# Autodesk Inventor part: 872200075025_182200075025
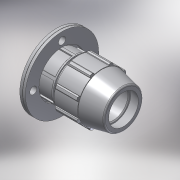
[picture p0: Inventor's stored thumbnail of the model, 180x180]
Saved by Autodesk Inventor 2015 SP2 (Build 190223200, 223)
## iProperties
Created: 2017-02
Part Number: 872200075025_182200075025
Material: PVC-Piping
Description: PLASSON COMPRESSION FLANGE ADAPTOR 75-2.1/2"
Document SubType Name: Modeling
Designer: KIM
Mass: 92.6774 g
Surface Area: 199.44 cm^2
Volume: 66.1981 cm^3
Density: 1.4 g/cm^3
Appearance: Smooth - White
Author: KIM
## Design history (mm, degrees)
derived "87220.ipt"
feature "Solid1::87220.ipt"
tag "TaggingFeature1"
body "Solid1"
other parameters: "d2" = 75, "d4" = 24.14286, "d5" = 54.08, "d7" = 132, "d9" = 24.14286, "d11" = 4.82857, "d12" = 105.6, "d13" = 120 deg, "d14" = 97.5, "d15" = 12 deg, "d18" = 3.75, "d19" = 35 deg, "d20" = 17.5 deg, "d21" = 122.76, "d23" = 0, "d25" = 360 deg, "d27" = 2.64, "d34" = 6.6, "d36" = 0, "d42" = 59.15, "d43" = 3.96, "d46" = 2.25, "d53" = 1.5, "d55" = 360 deg, "d70" = 169, "d71" = 185, "d72" = 65, "d73" = 14.08333, "d74" = 90 deg, "d75" = 0.3, "d76" = 185, "d77" = 18, "d78" = 72.5, "d80" = 0, "d82" = 360 deg, "d85" = 112.2, "d86" = 105.6, "d87" = 2.3125, "d88" = 0.3, "d93" = 8.45, "d94" = 157, "d95" = 65, "d_" = 75, "E_" = 132, "H_" = 169, "l_" = 157, "D_" = 185, "Dp_" = 145, "S_" = 18, "DN_" = 65
